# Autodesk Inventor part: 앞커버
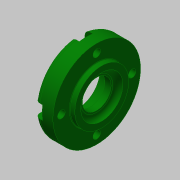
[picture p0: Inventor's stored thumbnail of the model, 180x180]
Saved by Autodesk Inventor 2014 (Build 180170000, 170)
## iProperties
Created: 2015-11
Part Number: 앞커버
Material: 알루미늄 6061
Document SubType Name: Modeling
Designer: mduedu
Density: 1 g/cm^3
Appearance: 진녹색
Author: mduedu
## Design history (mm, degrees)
sketch "스케치1"
  geometry: L1 (-7, 0)-(7, 0); L2 (-7, 0)-(-7, 26); L3 (-7, 26)-(4, 26); L4 (4, 26)-(4, 16); L5 (4, 16)-(7, 16); L6 (7, 16)-(7, 0); 2 further points
  constraints: 12 end point, 3 perpendicular, 2 parallel, 1 coincident, 1 horizontal, 1 midpoint
  dimensions: "d0" = 14 distance of L1.start L1.end; "d1" = 52 diameter of L3 L1; "d2" = 3 distance of L4.end L5.end; "d3" = 32 diameter of L5 L1
revolve "회전1" sketch "스케치1" stored, may be unused: angle "d4" = 90 deg
hole "구멍1" diameter "d7" = 25; stored, may be unused: countersink angle "d11" = 90 deg, drill point angle "d13" = 0 deg; dims "d5" = 10, "d6" = 10, "d8" = 6, "d9" = 4, "d10" = 2, "d12" = 3
hole "구멍2" diameter "d16" = 25; stored, may be unused: countersink angle "d20" = 90 deg, drill point angle "d22" = 0 deg; dims "d17" = 6, "d18" = 4, "d19" = 2, "d21" = 7.3, "d62" = 10, "d63" = 10
hole "구멍3" diameter "d25" = 17; stored, may be unused: countersink angle "d29" = 90 deg, drill point angle "d31" = 0 deg; dims "d23" = 10, "d24" = 10, "d26" = 6, "d27" = 4, "d28" = 2, "d30" = 4.2
chamfer "모따기1" distance "d32" = 0.7; stored, may be unused: second distance "d33" = 2, angle "d34" = 30 deg
fillet "모깎기1" dims "d35" = 0.3
fillet "모깎기2" dims "d36" = 3
fillet "모깎기3" dims "d37" = 3
fillet "모깎기4" dims "d38" = 0.3
sketch "스케치3" dims "d61" = 42
  geometry: C1 r 26 at (0, 0) reference; 2 further points
  constraints: 2 vertical alignment, 1 coincident, 2 other
hole "구멍4" sketch "스케치3" at (0, -21) diameter "d44" = 4.5; stored, may be unused: countersink angle "d48" = 90 deg, drill point angle "d50" = 0 deg; dims "d45" = 6, "d46" = 8, "d47" = 4.6, "d49" = 8
sketch "스케치4"
  geometry: L1 (-4, 0)-(-4, -4.69); L2 (4, 0)-(4, -4.69); A1 r 4 centre (0, 0) between (3.614, -1.714) and (-3.614, -1.714) reference; A2 r 26 centre (0, 21) between (-4, -4.69) and (4, -4.69) reference; 1 further point
  constraints: 4 end point, 4 point on circle, 2 tangent, 1 parallel, 1 vertical
extrude "돌출1" cut sketch "스케치4" stored distance "d51" = 0; taper "d52" = 0 deg
node "솔리드1"
pattern_circular "원형 패턴1" dims angle "d54" = 360 deg
